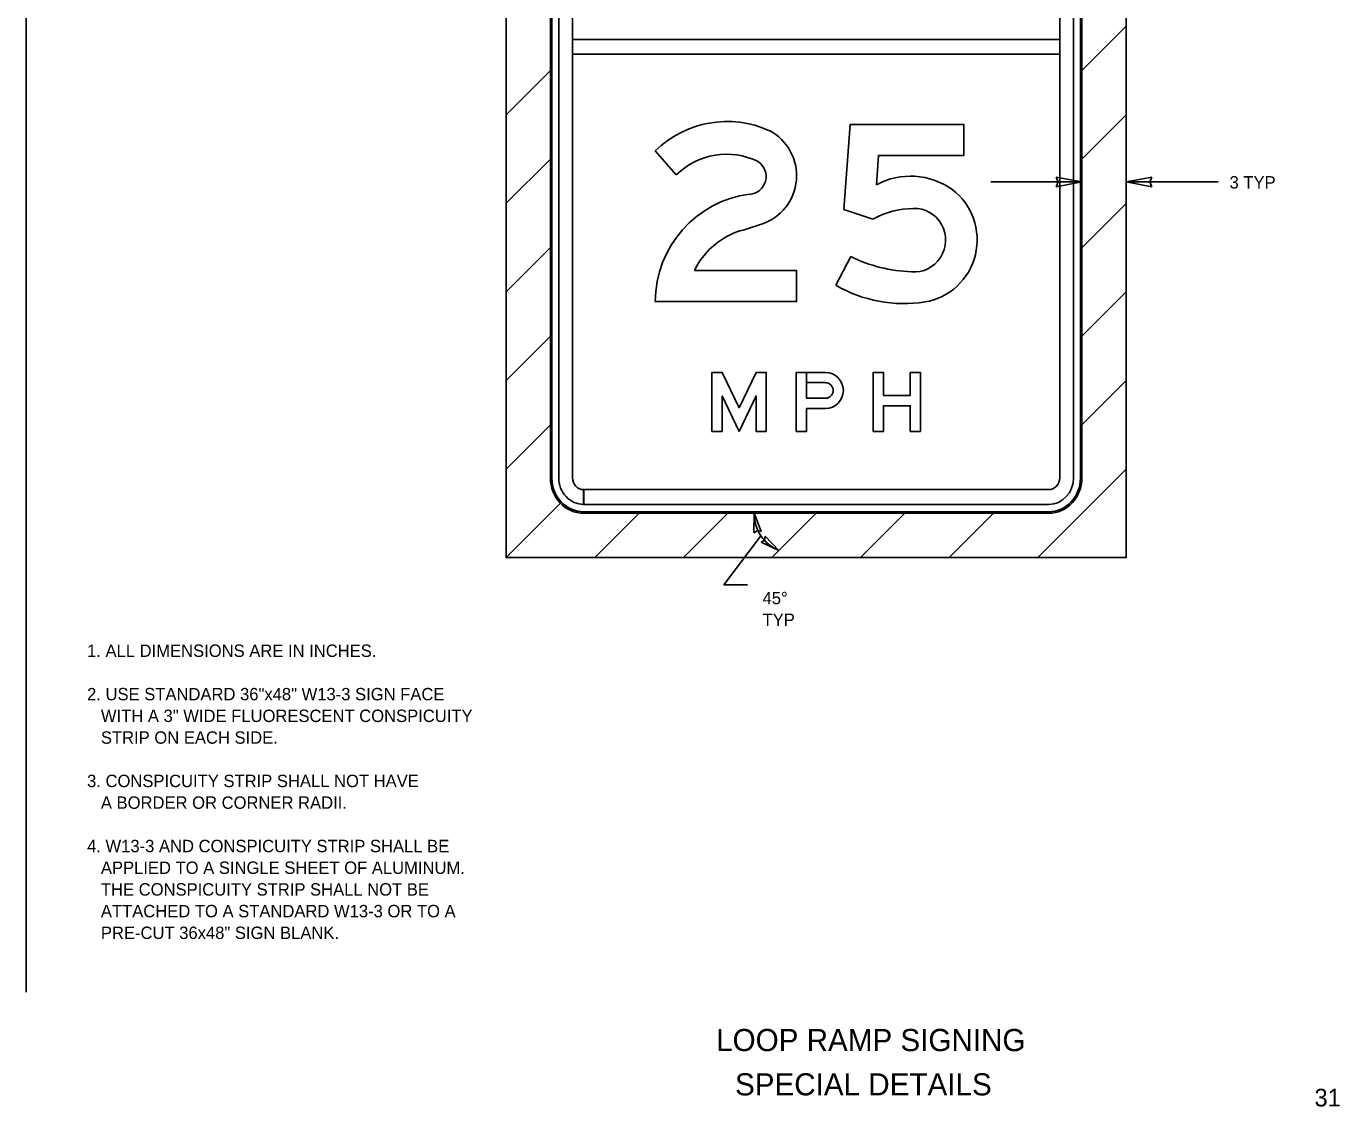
# Model space of a CAD drawing. Extents: x 582908 to 586041, y 1530940 to 1533040.
# Drawn here: x 584558 to 586041, y 1530991 to 1532211 of the extents above; entities that cross this region are included whole.
import ezdxf

# ---------------------------------------------------------------- set-up
doc = ezdxf.new("R2010")
doc.units = 0
for name, color, linetype in [('GSDims', 7, 'Continuous'), ('SheetLinesMisc2_dp', 7, 'Continuous'), ('SignPanel', 7, 'Continuous'), ('TextMisc', 7, 'Continuous'), ('TextNotes', 7, 'Continuous'), ('TextShtNo', 7, 'Continuous')]:
    doc.layers.add(name, color=color, linetype=linetype)

msp = doc.modelspace()

# ---------------------------------------------------------------- linework, layer by layer
at = {"layer": 'GSDims'}
for p, q in [((585750.1, 1532034.7), (585647.3, 1532034.7)), ((585750.1, 1532034.7), (585721.1, 1532040.3)), ((585721.1, 1532040.3), (585723.3, 1532034.7)), ((585723.3, 1532034.7), (585721.1, 1532029.3)), ((585721.1, 1532029.3), (585750.1, 1532034.7)), ((585829.1, 1532040.1), (585800.1, 1532034.7)), ((585904.1, 1532034.7), (585800.1, 1532034.7)), ((585800.1, 1532034.7), (585829.1, 1532029.1)), ((585826.9, 1532034.7), (585829.1, 1532040.1)), ((585829.1, 1532029.1), (585826.9, 1532034.7)), ((585380, 1531660.7), (585379.8, 1531638.5)), ((585387.9, 1531640), (585380, 1531660.7)), ((585346, 1531579.8), (585387.6, 1531635.3)), ((585379.8, 1531638.5), (585383.6, 1531640.9)), ((585383.6, 1531640.9), (585387.9, 1531640)), ((585392.7, 1531634.6), (585391.6, 1531630.2)), ((585407.9, 1531618.5), (585392.7, 1531634.6)), ((585391.6, 1531630.2), (585387.9, 1531627.9)), ((585387.9, 1531627.9), (585407.9, 1531618.5)), ((585346, 1531579.8), (585372.4, 1531579.8))]:
    msp.add_line(p, q, dxfattribs=at)
msp.add_arc((585424.4, 1531659.8), 44.2, 178.9271, 248.409, dxfattribs=at)
at = {"layer": 'SheetLinesMisc2_dp'}
msp.add_line((584558.3, 1533039.8), (584558.3, 1531119.8), dxfattribs=at)
at = {"layer": 'SignPanel'}
for p, q in [((585150.1, 1532420.5), (585150.1, 1531700.6)), ((585150.1, 1532420.5), (585150.1, 1531700.6)), ((585151.6, 1532420.5), (585151.6, 1531700.6)), ((585159.5, 1532420.5), (585159.5, 1531700.6)), ((585175.1, 1532420.5), (585175.1, 1531700.6)), ((585725.1, 1531700.6), (585725.1, 1532420.5)), ((585740.7, 1531700.6), (585740.7, 1532420.5)), ((585748.5, 1531700.6), (585748.5, 1532420.5)), ((585750.1, 1531700.6), (585750.1, 1532420.5)), ((585725.1, 1532195.5), (585175.1, 1532195.5)), ((585175.1, 1532195.5), (585175.1, 1532178.9)), ((585725.1, 1532195.5), (585175.1, 1532195.5)), ((585175.1, 1532195.5), (585175.1, 1532178.9)), ((585725.1, 1532195.5), (585175.1, 1532195.5)), ((585175.1, 1532195.5), (585175.1, 1532178.9)), ((585725.1, 1532178.9), (585725.1, 1532195.5)), ((585725.1, 1532178.9), (585725.1, 1532195.5)), ((585725.1, 1532178.9), (585725.1, 1532195.5)), ((585175.1, 1532178.9), (585725.1, 1532178.9)), ((585175.1, 1532178.9), (585725.1, 1532178.9)), ((585175.1, 1532178.9), (585725.1, 1532178.9)), ((585268.4, 1532069.9), (585292.1, 1532042.6)), ((585268.4, 1532069.9), (585292.1, 1532042.6)), ((585268.4, 1532069.9), (585292.1, 1532042.6)), ((585518.1, 1532031.6), (585518.1, 1532031.6)), ((585472.2, 1531918.1), (585489.1, 1531950.4)), ((585472.2, 1531918.1), (585489.1, 1531950.4)), ((585472.2, 1531918.1), (585489.1, 1531950.4)), ((585489.1, 1531950.4), (585489.1, 1531950.4)), ((585489.1, 1531950.4), (585489.1, 1531950.4)), ((585460.7, 1531790.6), (585439.1, 1531790.6)), ((585439.1, 1531778.9), (585460.7, 1531778.9)), ((585151.7, 1531700.6), (585151.6, 1531700.6)), ((585748.5, 1531700.6), (585748.5, 1531700.6)), ((585187.6, 1531670.6), (585187.6, 1531687.3)), ((585187.7, 1531687.3), (585712.6, 1531687.3)), ((585187.7, 1531687.3), (585187.7, 1531670.6)), ((585187.6, 1531660.6), (585187.6, 1531662.3)), ((585187.6, 1531662.3), (585187.6, 1531662.3)), ((585187.6, 1531662.3), (585712.6, 1531662.3)), ((585187.6, 1531662.3), (585187.6, 1531660.6)), ((585187.7, 1531670.6), (585712.6, 1531670.6)), ((585712.6, 1531662.3), (585712.6, 1531662.3)), ((585187.6, 1531660.6), (585712.6, 1531660.6))]:
    msp.add_line(p, q, dxfattribs=at)
for points in [[(585100.1, 1532510.5), (585800.1, 1532510.5), (585800.1, 1531610.6), (585100.1, 1531610.6)], [(585343.9, 1531793.2), (585363.1, 1531753.1), (585382.3, 1531793.2), (585382.3, 1531753.1), (585393.8, 1531753.1), (585393.8, 1531819.7), (585382.2, 1531819.7), (585363.1, 1531779.8), (585344, 1531819.7), (585332.4, 1531819.7), (585332.4, 1531753.1), (585343.9, 1531753.1)], [(585343.9, 1531793.2), (585363.1, 1531753.1), (585382.3, 1531793.2), (585382.3, 1531753.1), (585393.8, 1531753.1), (585393.8, 1531819.7), (585382.2, 1531819.7), (585363.1, 1531779.8), (585344, 1531819.7), (585332.4, 1531819.7), (585332.4, 1531753.1), (585343.9, 1531753.1)], [(585343.9, 1531793.2), (585363.1, 1531753.1), (585382.3, 1531793.2), (585382.3, 1531753.1), (585393.8, 1531753.1), (585393.8, 1531819.7), (585382.2, 1531819.7), (585363.1, 1531779.8), (585344, 1531819.7), (585332.4, 1531819.7), (585332.4, 1531753.1), (585343.9, 1531753.1)], [(585556.3, 1531793.7), (585526.1, 1531793.7), (585526.1, 1531819.7), (585514.6, 1531819.7), (585514.6, 1531753.1), (585526.1, 1531753.1), (585526.1, 1531782), (585556.3, 1531782), (585556.3, 1531753.1), (585567.8, 1531753.1), (585567.8, 1531819.7), (585556.3, 1531819.7)], [(585556.3, 1531793.7), (585526.1, 1531793.7), (585526.1, 1531819.7), (585514.6, 1531819.7), (585514.6, 1531753.1), (585526.1, 1531753.1), (585526.1, 1531782), (585556.3, 1531782), (585556.3, 1531753.1), (585567.8, 1531753.1), (585567.8, 1531819.7), (585556.3, 1531819.7)], [(585556.3, 1531793.7), (585526.1, 1531793.7), (585526.1, 1531819.7), (585514.6, 1531819.7), (585514.6, 1531753.1), (585526.1, 1531753.1), (585526.1, 1531782), (585556.3, 1531782), (585556.3, 1531753.1), (585567.8, 1531753.1), (585567.8, 1531819.7), (585556.3, 1531819.7)]]:
    msp.add_lwpolyline(points, close=True, dxfattribs=at)
for points in [[(585750.1, 1532060.5), (585800.1, 1532110.5), (585800.1, 1532210.5), (585750.1, 1532160.5), (585750.1, 1532060.5)], [(585150.1, 1532060.6), (585150.1, 1532160.6), (585100.1, 1532110.6), (585100.1, 1532010.6), (585150.1, 1532060.6)], [(585514, 1531992.9), (585481.5, 1532003.8), (585488.6, 1532099.7), (585616.9, 1532099.7), (585616.9, 1532064.7), (585520.6, 1532064.7), (585518.1, 1532031.6)], [(585514, 1531992.9), (585481.5, 1532003.8), (585488.6, 1532099.7), (585616.9, 1532099.7), (585616.9, 1532064.7), (585520.6, 1532064.7), (585518.1, 1532031.6)], [(585514, 1531992.9), (585481.5, 1532003.8), (585488.6, 1532099.7), (585616.9, 1532099.7), (585616.9, 1532064.7), (585520.6, 1532064.7), (585518.1, 1532031.6)], [(585750.1, 1531860.5), (585800.1, 1531910.5), (585800.1, 1532010.5), (585750.1, 1531960.5), (585750.1, 1531860.5)], [(585150.1, 1531860.6), (585150.1, 1531960.6), (585100.1, 1531910.6), (585100.1, 1531810.6), (585150.1, 1531860.6)], [(585268.4, 1531899.7), (585427.9, 1531899.7), (585427.9, 1531934.7), (585312.6, 1531934.7)], [(585268.4, 1531899.7), (585427.9, 1531899.7), (585427.9, 1531934.7), (585312.6, 1531934.7)], [(585268.4, 1531899.7), (585427.9, 1531899.7), (585427.9, 1531934.7), (585312.6, 1531934.7)], [(585460.7, 1531819.7), (585427.6, 1531819.7), (585427.6, 1531753.1), (585439.1, 1531753.1), (585439.1, 1531778.9)], [(585439.1, 1531819.7), (585427.6, 1531819.7), (585427.6, 1531753.1), (585439.1, 1531753.1), (585439.1, 1531778.9), (585460.7, 1531778.9)], [(585439.1, 1531819.7), (585427.6, 1531819.7), (585427.6, 1531753.1), (585439.1, 1531753.1), (585439.1, 1531778.9), (585460.7, 1531778.9)], [(585460.7, 1531819.7), (585439.1, 1531819.7), (585439.1, 1531808.1), (585460.7, 1531808.1)], [(585460.7, 1531790.6), (585439.1, 1531790.6), (585439.1, 1531819.7)], [(585460.7, 1531819.7), (585439.1, 1531819.7), (585439.1, 1531808.1), (585460.7, 1531808.1)], [(585460.7, 1531790.6), (585439.1, 1531790.6), (585439.1, 1531819.7)], [(585712.6, 1531660.6), (585650.2, 1531660.6), (585600.2, 1531610.6), (585700.2, 1531610.6), (585800.1, 1531710.5), (585800.1, 1531810.5), (585750.1, 1531760.5)], [(585439.1, 1531790.6), (585439.1, 1531808.1), (585460.7, 1531808.1)], [(585150.1, 1531700.6), (585150.1, 1531760.6), (585100.1, 1531710.6), (585100.1, 1531610.6), (585161.5, 1531671.9)], [(585750.1, 1531760.5), (585750.1, 1531700.6)], [(585300.2, 1531610.6), (585350.2, 1531660.6), (585250.2, 1531660.6), (585200.2, 1531610.6), (585300.2, 1531610.6)], [(585500.2, 1531610.6), (585550.2, 1531660.6), (585450.2, 1531660.6), (585400.2, 1531610.6), (585500.2, 1531610.6)]]:
    msp.add_lwpolyline(points, dxfattribs=at)
for centre, major_axis, ratio, start_param, end_param in [((585349.5, 1531984.2), (0, 118.8), 0.985, 5.861869, 7.048709), ((585349.5, 1531984.2), (0, 118.8), 0.985, 5.861869, 7.048709), ((585349.5, 1531984.2), (0, 118.8), 0.985, 5.861869, 7.048709), ((585371.6, 1532041.8), (0, 57.2), 0.985, 3.445077, 5.80948), ((585371.6, 1532041.8), (0, 57.2), 0.985, 3.445077, 5.80948), ((585371.6, 1532041.8), (0, 57.2), 0.985, 3.445077, 5.80948), ((585349, 1531983), (0, 83), 0.985, 5.833638, 7.052577), ((585349, 1531983), (0, 83), 0.985, 5.833638, 7.052577), ((585349, 1531983), (0, 83), 0.985, 5.833638, 7.052577), ((585373.8, 1532040.8), (0, 20.1), 0.985, 3.193411, 5.709913), ((585373.8, 1532040.8), (0, 20.1), 0.985, 3.193411, 5.709913), ((585373.8, 1532040.8), (0, 20.1), 0.985, 3.193411, 5.709913), ((585556.5, 1531957.7), (0, 83.6), 0.985, 5.674797, 6.76791), ((585556.5, 1531957.7), (0, 83.6), 0.985, 5.674797, 6.76791), ((585556.5, 1531957.7), (0, 83.6), 0.985, 5.674797, 6.76791), ((585389.5, 1531898.7), (0, 123), 0.985, 0.121378, 1.562513), ((585389.5, 1531898.7), (0, 123), 0.985, 0.121378, 1.562513), ((585389.5, 1531898.7), (0, 123), 0.985, 0.121378, 1.562513), ((585562, 1531969.3), (0, 70.9), 0.985, 3.29706, 5.646286), ((585562, 1531969.3), (0, 70.9), 0.985, 3.29706, 5.646286), ((585562, 1531969.3), (0, 70.9), 0.985, 3.29706, 5.646286), ((585562.1, 1531899.7), (0, 105.2), 0.985, 0.021733, 0.482857), ((585562.1, 1531899.7), (0, 105.2), 0.985, 0.021733, 0.482857), ((585562.1, 1531899.7), (0, 105.2), 0.985, 0.021733, 0.482857), ((585560.8, 1531969), (0, 35.9), 0.985, 3.050128, 6.31212), ((585560.8, 1531969), (0, 35.9), 0.985, 3.050128, 6.31212), ((585560.8, 1531969), (0, 35.9), 0.985, 3.050128, 6.31212), ((585179.7, 1532612.1), (0, 659.8), 0.985, 3.423454, 3.46857), ((585179.7, 1532612.1), (0, 659.8), 0.985, 3.423454, 3.46857), ((585179.7, 1532612.1), (0, 659.8), 0.985, 3.423454, 3.46857), ((585391.2, 1531894.7), (0, 89.3), 0.985, 0.357174, 1.105945), ((585391.2, 1531894.7), (0, 89.3), 0.985, 0.357174, 1.105945), ((585391.2, 1531894.7), (0, 89.3), 0.985, 0.357174, 1.105945), ((585564.8, 1532112.6), (0, 179.5), 0.985, 2.699218, 3.100889), ((585564.8, 1532112.6), (0, 179.5), 0.985, 2.699218, 3.100889), ((585564.8, 1532112.6), (0, 179.5), 0.985, 2.699218, 3.100889), ((585549.4, 1532056.2), (0, 158.8), 0.985, 2.625811, 3.292278), ((585549.4, 1532056.2), (0, 158.8), 0.985, 2.625811, 3.292278), ((585549.4, 1532056.2), (0, 158.8), 0.985, 2.625811, 3.292278), ((585460.7, 1531799.3), (0, 20.4), 0.985, 3.141593, 6.283185), ((585460.7, 1531799.3), (0, 20.4), 0.985, 3.141593, 6.283185), ((585460.7, 1531799.3), (0, 20.4), 0.985, 3.141593, 6.283185), ((585460.7, 1531799.3), (0, 8.75), 0.985, 3.141593, 6.283185), ((585460.7, 1531799.3), (0, 8.75), 0.985, 3.141593, 6.283185), ((585460.7, 1531799.3), (0, 8.75), 0.985, 3.141593, 6.283185), ((585187.6, 1531700.6), (0, 40), 0.937555, 1.570796, 2.370551), ((585187.6, 1531700.6), (0, 40), 0.937555, 1.570796, 3.141593), ((585187.6, 1531700.6), (0, 38.3), 0.937555, 1.570796, 3.141593), ((585187.6, 1531700.6), (0, 30), 0.937555, 1.570796, 3.141593), ((585187.6, 1531700.6), (0, 13.3), 0.937555, 1.570796, 3.141593), ((585712.6, 1531700.6), (0, 40), 0.937555, 3.141593, 4.712389), ((585712.6, 1531700.6), (0, 40), 0.937555, 3.141593, 4.712389), ((585712.6, 1531700.6), (0, 30), 0.937555, 3.141593, 4.712389), ((585712.6, 1531700.6), (0, 13.3), 0.937555, 3.141593, 4.712389), ((585712.6, 1531700.6), (0, 40), 0.937555, 3.141593, 4.712389), ((585712.6, 1531700.6), (0, 38.3), 0.937555, 3.141593, 4.712389)]:
    msp.add_ellipse(centre, major_axis=major_axis, ratio=ratio, start_param=start_param, end_param=end_param, dxfattribs=at)

# ---------------------------------------------------------------- texts
at = {"layer": 'GSDims'}
for s, p in [('3 TYP', (585916.8, 1532027.3)), ('45°', (585389.6, 1531557.9)), ('TYP', (585389.6, 1531533.4))]:
    msp.add_text(s, height=14, dxfattribs=at).set_placement(p)
at = {"layer": 'TextMisc'}
for s, p in [('   LOOP RAMP SIGNING    ', (585309.3, 1531053.3)), ('    SPECIAL DETAILS     ', (585321.3, 1531003.3))]:
    msp.add_text(s, height=25, rotation=360, dxfattribs=at).set_placement(p)
at = {"layer": 'TextNotes'}
for s, p in [('1. ALL DIMENSIONS ARE IN INCHES.', (584627, 1531498.4)), ('2. USE STANDARD 36"x48" W13-3 SIGN FACE', (584627, 1531449.4)), ('   WITH A 3" WIDE FLUORESCENT CONSPICUITY ', (584627, 1531424.9)), ('   STRIP ON EACH SIDE. ', (584627, 1531400.4)), ('3. CONSPICUITY STRIP SHALL NOT HAVE', (584627, 1531351.4)), ('   A BORDER OR CORNER RADII.', (584627, 1531326.9)), ('4. W13-3 AND CONSPICUITY STRIP SHALL BE', (584627, 1531277.9)), ('   APPLIED TO A SINGLE SHEET OF ALUMINUM.', (584627, 1531253.4)), ('   THE CONSPICUITY STRIP SHALL NOT BE ', (584627, 1531228.9)), ('   ATTACHED TO A STANDARD W13-3 OR TO A', (584627, 1531204.4)), ('   PRE-CUT 36x48" SIGN BLANK.', (584627, 1531179.9))]:
    msp.add_text(s, height=14, dxfattribs=at).set_placement(p)
at = {"layer": 'TextShtNo'}
msp.add_text('31', height=20, rotation=360, dxfattribs=at).set_placement((586012.7, 1530990.8))

doc.saveas('drawing.dxf')
